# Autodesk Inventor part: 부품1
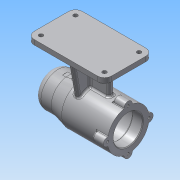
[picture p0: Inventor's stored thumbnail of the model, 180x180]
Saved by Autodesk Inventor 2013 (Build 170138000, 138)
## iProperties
Created: 2019-07
Part Number: 부품1
Material: 알루미늄 6061
Document SubType Name: Modeling
Designer: Administrator
Density: 2.71 g/cm^3
Mass: 645.341 g
Surface Area: 655.431 cm^2
Volume: 238.133 cm^3
Author: Administrator
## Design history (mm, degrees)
sketch "스케치1"
  geometry: L1 (0, 0)-(112, 0); L2 (0, 0)-(0, 15); L3 (10, 25)-(25, 25); L4 (25, 25)-(45, 30); L5 (45, 30)-(95.471, 30); L6 (111.471, 21)-(96.471, 21); L7 (96.471, 21)-(96.471, 21); L8 (93.471, 24)-(45.471, 24); L9 (42.471, 21)-(42.471, 21); L10 (42.471, 21)-(30.771, 21); L11 (30.471, 20.7)-(30.471, 17.5); L12 (30.471, 17.5)-(12.771, 17.5); L13 (12.471, 17.2)-(12.471, 16); L14 (12.471, 16)-(8.771, 16); L15 (8.471, 15.7)-(8.471, 10.5); L16 (8.471, 10.5)-(8.471, 10.5); L17 (5.471, 7.5)-(5.471, 0); L18 (95.471, 30)-(111.471, 30); L19 (111.471, 30)-(111.471, 21); A1 r 3 centre (45.471, 21) between (45.471, 24) and (42.471, 21); A2 r 3 centre (93.471, 21) between (96.471, 21) and (93.471, 24); A3 r 10 centre (10, 15) between (10, 25) and (0, 15); A4 r 3 centre (8.471, 7.5) between (8.471, 10.5) and (5.471, 7.5); A5 r 0.3 centre (8.771, 15.7) between (8.771, 16) and (8.471, 15.7); A6 r 0.3 centre (12.771, 17.2) between (12.771, 17.5) and (12.471, 17.2); A7 r 0.3 centre (30.771, 20.7) between (30.771, 21) and (30.471, 20.7); 7 further points
  constraints: 38 end point, 15 point on line, 14 point on circle, 14 tangent, 11 perpendicular, 7 centre point, 6 parallel, 4 equal radius, 1 horizontal
  dimensions: "d0" = 112 distance of L1.start L1.end; "d1" = 42 diameter of L6.start L1; "d2" = 48 diameter of point (96.471, 24) L1; "d3" = 42 diameter of L9.end L1; "d4" = 35 diameter of L11.end L1; "d5" = 32 diameter of L13.end L1; "d6" = 21 diameter of point (5.471, 10.5) L1; "d7" = 3 distance of L15.end point (5.471, 10.5); "d8" = 4 distance of L13.end point (8.471, 16); "d9" = 18 distance of L11.end point (12.471, 17.5); "d10" = 12 distance of L9.end point (30.471, 21); "d11" = 54 distance of point (96.471, 24) point (42.471, 24); "d12" = 15 distance of L6.start L6.end; "d13" = 50 diameter of point (0, 25) L1; "d14" = 60 diameter of L4.end L1; "d15" = 25 distance of L3.end point (0, 25); "d16" = 45 horizontal distance of L4.end point (0, 25); "d18" = 3 radius of A1; "d19" = 10 radius of A3; "d85" = 0.3 radius of A5
revolve "회전1" sketch "스케치1" stored, may be unused: angle "d20" = 90 deg
sketch "스케치2"
  geometry: C1 r 6 at (0.065, 30); C2 r 6 at (-29.998, -0.304); C3 r 6 at (0.064, -30); C4 r 6 at (30, -0.135); A1 r 30 centre (0, 0) between (0.065, 30) and (-29.998, -0.304) reference; A2 r 30 centre (0, 0) between (0.065, 30) and (-29.998, -0.304)
  constraints: 8 point on circle, 5 centre point, 1 coincident, 1 concentric
  dimensions: "d21" = 12 diameter of C1; "d22" = 12 diameter of C2; "d23" = 12 diameter of C3; "d24" = 12 diameter of C4
extrude "돌출1" join sketch "스케치2" distance "d25" = 16; taper "d26" = 0 deg
sketch "스케치4"
  geometry: L1 (0, 70)-(0, 80); L2 (0, 80)-(-112, 80); L3 (-112, 80)-(-112, 70); L4 (-112, 70)-(0, 70); L5 (0, 70)-(0, 80); 1 further point
  constraints: 10 end point, 2 equal length, 1 perpendicular, 1 vertical
  dimensions: "d29" = 80 distance of L1.end point (0, 0); "d30" = 112 distance of L1.end L2.end; "d31" = 10 distance of L2.end L3.end; "d32" = 112 distance of L1.start L3.end
extrude "돌출2" join sketch "스케치4" stored distance "d33" = 70; taper "d34" = 0 deg
sketch "스케치5"
  geometry: L1 (0, -70)-(0, 0) reference; L2 (112, -70)-(0, -70) reference; L3 (0, -35)-(25, -35); L4 (25, -35)-(25, -39); L5 (25, -35)-(25, -31); L6 (25, -35)-(56, -35); L7 (56, -35)-(56, -7); L8 (56, -35)-(56, -63); L9 (56, -7)-(52, -7); L10 (56, -7)-(60, -7); L11 (60, -7)-(60, -63); L12 (60, -63)-(52, -63); L13 (52, -63)-(52, -39); L14 (25, -39)-(52, -39); L15 (25, -31)-(52, -31); L16 (52, -31)-(52, -7); L17 (112, -35)-(92, -35); L18 (92, -35)-(60, -35); L19 (60, -39)-(92, -39); L20 (92, -39)-(92, -35); L21 (92, -35)-(92, -31); L22 (92, -31)-(60, -31)
  constraints: 40 end point, 10 perpendicular, 5 parallel, 4 collinear, 2 midpoint, 2 point on line
  dimensions: "d35" = 25 distance of L3.start L3.end; "d36" = 4 distance of L3.end L4.end; "d37" = 4 distance of L3.end L5.end; "d38" = 31 distance of L3.end L6.end; "d39" = 28 distance of L6.end L7.end; "d40" = 28 distance of L6.end L8.end; "d41" = 4 distance of L7.end L9.end; "d42" = 4 distance of L7.end L10.end; "d43" = 20 distance of L17.start L17.end; "d44" = 4 distance of L17.end L21.end
extrude "돌출3" join sketch "스케치5" stored distance "d45" = 70; taper "d46" = 0 deg
sketch "스케치6"
  geometry: L1 (0, 45.322)-(5, 45.322) reference; L2 (0, 0)-(0, 45.322) reference; L3 (0, 0)-(15.449, 42.446); L4 (0, 0)-(45.17, 0); L5 (0, 45.322)-(0, 0); L6 (15.449, 42.446)-(15.527, 42.659); L7 (15.527, 42.659)-(5, 45.322); L8 (0, 45.322)-(5, 45.322); 2 further points
  constraints: 12 end point, 3 collinear, 1 equal length, 1 horizontal, 2 other
  dimensions: "d47" = 70 deg angle of L4 L3
extrude "돌출4" cut sketch "스케치6" distance "d48" = 70; taper "d49" = 0 deg
sketch "스케치7"
  geometry: L1 (0, 24)-(59.23, 24) reference; L2 (0, 0)-(40.268, 0) reference; L3 (0, 24)-(45.506, 15.976); L4 (0, 24)-(46.208, 24); L5 (45.506, 15.976)-(47.334, 15.654); L6 (0, 24)-(59.23, 24); A1 r 30 centre (70, -4) between (59.23, 24) and (40.268, 0) reference; A2 r 30 centre (70, -4) between (59.23, 24) and (47.334, 15.654)
  constraints: 9 end point, 4 point on circle, 2 point on line, 1 centre point, 1 coincident, 1 collinear, 1 equal length, 1 horizontal
  dimensions: "d50" = 10 deg angle of L3 L4
extrude "돌출5" cut sketch "스케치7" distance "d51" = 70; taper "d52" = 0 deg
sketch "스케치8"
  geometry: L1 (0, 24)-(40.268, 24) reference; L2 (0, 0)-(46.46, 8.192); L3 (0, 0)-(47.177, 0); L4 (46.46, 8.192)-(47.334, 8.346); L5 (0, 0)-(59.23, 0); A1 r 30 centre (70, 28) between (40.268, 24) and (59.23, 0) reference; A2 r 30 centre (70, 28) between (47.334, 8.346) and (59.23, 0)
  constraints: 9 end point, 3 point on circle, 2 collinear, 1 centre point, 1 coincident, 1 equal length, 1 horizontal, 1 point on line
  dimensions: "d53" = 10 deg angle of L3 L2
extrude "돌출6" cut sketch "스케치8" distance "d54" = 70; taper "d55" = 0 deg
fillet "모깎기1" dims "d56" = 10
sketch "스케치9"
  geometry: C1 r 3 at (0, -10); C2 r 3 at (0, -60); C3 r 3 at (92, -10); C4 r 3 at (92, -60); A1 r 10 centre (92, -60) between (92, -70) and (102, -60) reference; A2 r 10 centre (92, -10) between (102, -10) and (92, 0) reference; A3 r 10 centre (0, -10) between (0, 0) and (-10, -10) reference; A4 r 10 centre (0, -60) between (-10, -60) and (0, -70) reference; 1 further point
  constraints: 4 centre point, 4 coincident
  dimensions: "d57" = 6 diameter of C1; "d58" = 6 diameter of C2; "d59" = 6 diameter of C3; "d60" = 6 diameter of C4
extrude "돌출7" cut sketch "스케치9" distance "d61" = 70; taper "d62" = 0 deg
node "작업 평면2"
sketch "스케치11"
  geometry: L1 (-111.471, -36)-(-111.471, -29.373) reference; 3 further points
  constraints: 1 other
  dimensions: "d65" = 42 distance from line of L1 point (-69.471, 0); "d66" = 0 vertical distance of point (0, 0) point (-69.471, 0)
feature "엠보싱1" sketch "스케치11" dims "d67" = 0.5, "d68" = 0
fillet "모깎기3" dims "d69" = 3
fillet "모깎기4" dims "d70" = 3
fillet "모깎기5" dims "d71" = 3
chamfer "모따기1" distance "d72" = 1; stored, may be unused: second distance "d73" = 2, angle "d74" = 45 deg
sketch "스케치12"
  geometry: C1 r 22 at (-30, 0) reference; A1 r 6 centre (-30.07, 30) between (-24.099, 29.414) and (-36.039, 29.386) reference; A2 r 6 centre (-59.997, -0.439) between (-59.484, 5.539) and (-59.309, -6.4) reference; A3 r 6 centre (-29.8, -29.999) between (-35.774, -29.439) and (-23.835, -29.36) reference; A4 r 6 centre (0, 0) between (-0.6, -5.97) and (-0.6, 5.97) reference; 9 further points
  constraints: 1 coincident, 1 horizontal alignment, 2 other
hole "구멍1" sketch "스케치12" at (0, 0), (-30.07, 30), (-59.997, -0.439), (-29.8, -29.999) diameter "d78" = 3.242; stored, may be unused: countersink angle "d82" = 90 deg, drill point angle "d84" = 118 deg; dims "d79" = 8, "d80" = 4, "d81" = 2, "d83" = 11
chamfer "모따기2" distance "d86" = 3; stored, may be unused: second distance "d87" = 2, angle "d88" = 45 deg
fillet "모깎기9" dims "d89" = 1
fillet "모깎기10" dims "d90" = 2
node "솔리드1"
